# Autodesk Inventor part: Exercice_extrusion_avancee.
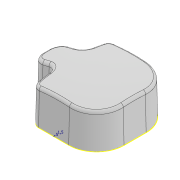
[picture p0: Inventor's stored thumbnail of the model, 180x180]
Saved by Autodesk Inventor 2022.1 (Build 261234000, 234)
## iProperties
Created: 2019-12
Part Number: Exercice_extrusion_avancee.
Material: Générique
Document SubType Name: Modeling
Designer: Fabian
Density: 1 g/cm^3
Appearance: Par défaut
Mass: 114.286 g
Surface Area: 775.892 cm^2
Volume: 114.286 cm^3
Author: Fabian
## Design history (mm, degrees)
sketch "Esquisse1"
  geometry: L1 (0, 70)-(0, -66.117); L2 (90, 0)-(-70, 0); L3 (90, 14.325)-(90, 0); L4 (-70, 45)-(-70, 0); L5 (44.578, 70)-(-45, 70); L6 (86.745, 24.649)-(60.961, 61.472); L7 (83, 0)-(83, 5); L8 (65, 23)-(55, 23); L9 (43, 35)-(43, 51); L10 (31, 63)-(-18, 63); L11 (-63, 18)-(-63, 0); L12 (-63, -18)-(-63, 0); L13 (0, -70)-(0, 66.117); L14 (-70, -45)-(-70, 0); L15 (31, -63)-(-18, -63); L16 (44.578, -70)-(-45, -70); L17 (43, -35)-(43, -51); L18 (90, -14.325)-(90, 0); L19 (86.745, -24.649)-(60.961, -61.472); L20 (83, 0)-(83, -5); L21 (65, -23)-(55, -23); C1 r 4 at (-60, 60); C2 r 6 at (55, 35); C3 r 4 at (-60, -60); C4 r 6 at (55, -35); A1 r 15 centre (-60, 60) between (-51, 72) and (-72, 51); A2 r 12 centre (55, 35) between (43, 35) and (55, 23); A3 r 12 centre (31, 51) between (43, 51) and (31, 63); A4 r 18 centre (72, 14.325) between (90, 14.325) and (86.745, 24.649); A5 r 20 centre (44.578, 50) between (60.961, 61.472) and (44.578, 70); A6 r 10 centre (-45, 80) between (-51, 72) and (-45, 70); A7 r 10 centre (-80, 45) between (-70, 45) and (-72, 51); A8 r 18 centre (65, 5) between (83, 5) and (65, 23); A9 r 45 centre (-18, 18) between (-18, 63) and (-63, 18); A10 r 45 centre (-18, -18) between (-63, -18) and (-18, -63); A11 r 12 centre (31, -51) between (31, -63) and (43, -51); A12 r 10 centre (-45, -80) between (-45, -70) and (-51, -72); A13 r 15 centre (-60, -60) between (-72, -51) and (-51, -72); A14 r 10 centre (-80, -45) between (-72, -51) and (-70, -45); A15 r 12 centre (55, -35) between (55, -23) and (43, -35); A16 r 20 centre (44.578, -50) between (44.578, -70) and (60.961, -61.472); A17 r 18 centre (65, -5) between (65, -23) and (83, -5); A18 r 18 centre (72, -14.325) between (86.745, -24.649) and (90, -14.325); 7 further points
  constraints: 44 end point, 40 point on circle, 32 symmetric about line, 22 centre point, 16 tangent, 14 point on line, 5 perpendicular, 4 coincident, 3 vertical, 2 horizontal, 11 other
  dimensions: "d2" = 70 distance between parallel lines of L4 L1; "d3" = 90 distance between parallel lines of L3 L1; "d5" = 30 diameter of A1; "d6" = 140 diameter of L5 L2; "d7" = 20 distance of point (90, 20) L2.start; "d8" = 35 deg angle of L3 L6; "d9" = 120 diameter of A1.centre L2; "d11" = 60 distance from line of A1.centre L1; "d12" = 8 diameter of C1; "d13" = 70 diameter of C2.centre L2; "d14" = 55 distance from line of C2.centre L1; "d15" = 12 diameter of C2; "d16" = 83 distance between parallel lines of L7 L1; "d17" = 63 distance between parallel lines of L11 L1; "d18" = 46 diameter of L8 L2 (derived); "d19" = 126 diameter of L10 L2; "d21" = 12 radius of A2; "d22" = 43 distance between parallel lines of L9 L1 (derived); "d23" = 12 radius of A3 (derived); "d24" = 18 radius of A4 (derived); "d25" = 20 radius of A5; "d26" = 10 radius of A6; "d27" = 10 radius of A7; "d28" = 18 radius of A8; "d29" = 45 radius of A9
extrude "Extrusion1" new body sketch "Esquisse1" distance "d30" = 65; taper "d31" = -1 deg
sketch "Esquisse2"
  geometry: L1 (-81.865, 65)-(61.865, 65); L2 (0, -455)-(0, 65); L3 (18, 65)-(-31, 65) reference; L4 (-55, 65)-(-65, 65) reference; A1 r 260 centre (0, -195) between (0, -455) and (0, 65); 1 further point
  constraints: 4 end point, 2 point on circle, 1 centre point, 1 collinear, 1 point on line, 1 tangent, 1 vertical, 1 vertical alignment
  dimensions: "d32" = 520 diameter of A1
revolve "Révolution1" sketch "Esquisse2" stored, may be unused: angle "d33" = 90 deg
fillet "Congé1" dims "d36" = 5
feature "Coque1" dims "d37" = 3
sketch "Esquisse3"
  geometry: L1 (-80, -5)-(-80, 5) reference; L2 (-65, 20)-(-55, 20) reference; L3 (-40, 35)-(-40, 51) reference; L4 (-31, 60)-(18, 60) reference; L5 (60, 18)-(60, -18) reference; L6 (18, -60)-(-31, -60) reference; L7 (-40, -51)-(-40, -35) reference; L8 (-55, -20)-(-65, -20) reference; L9 (-31, 63)-(18, 63) reference; L10 (-43, 35)-(-43, 51) reference; L11 (-65, 23)-(-55, 23) reference; L12 (-83, -5)-(-83, 5) reference; L13 (-55, -23)-(-65, -23) reference; L14 (-43, -51)-(-43, -35) reference; L15 (18, -63)-(-31, -63) reference; L16 (63, 18)-(63, -18) reference; L17 (18, 55)-(-31, 55); L18 (-35, 51)-(-35, 35); L19 (-55, 15)-(-65, 15); L20 (-75, 5)-(-75, -5); L21 (-65, -15)-(-55, -15); L22 (-35, -35)-(-35, -51); L23 (-31, -55)-(18, -55); L24 (55, -18)-(55, 18); L25 (-31, 56.5)-(18, 56.5); L26 (56.5, 18)-(56.5, -18); L27 (18, -56.5)-(-31, -56.5); L28 (-36.5, -51)-(-36.5, -35); L29 (-55, -16.5)-(-65, -16.5); L30 (-76.5, -5)-(-76.5, 5); L31 (-65, 16.5)-(-55, 16.5); L32 (-36.5, 35)-(-36.5, 51); A1 r 15 centre (-65, -5) between (-80, -5) and (-65, -20) reference; A2 r 15 centre (-65, 5) between (-65, 20) and (-80, 5) reference; A3 r 15 centre (-55, 35) between (-55, 20) and (-40, 35) reference; A4 r 9 centre (-31, 51) between (-31, 60) and (-40, 51) reference; A5 r 42 centre (18, 18) between (60, 18) and (18, 60) reference; A6 r 42 centre (18, -18) between (18, -60) and (60, -18) reference; A7 r 9 centre (-31, -51) between (-40, -51) and (-31, -60) reference; A8 r 15 centre (-55, -35) between (-40, -35) and (-55, -20) reference; A9 r 12 centre (-31, 51) between (-31, 63) and (-43, 51) reference; A10 r 12 centre (-55, 35) between (-55, 23) and (-43, 35) reference; A11 r 18 centre (-65, 5) between (-65, 23) and (-83, 5) reference; A12 r 18 centre (-65, -5) between (-83, -5) and (-65, -23) reference; A13 r 12 centre (-55, -35) between (-43, -35) and (-55, -23) reference; A14 r 12 centre (-31, -51) between (-43, -51) and (-31, -63) reference; A15 r 45 centre (18, -18) between (18, -63) and (63, -18) reference; A16 r 45 centre (18, 18) between (63, 18) and (18, 63) reference; A17 r 4 centre (-31, 51) between (-31, 55) and (-35, 51); A18 r 20 centre (-55, 35) between (-55, 15) and (-35, 35); A19 r 10 centre (-65, 5) between (-65, 15) and (-75, 5); A20 r 10 centre (-65, -5) between (-75, -5) and (-65, -15); A21 r 20 centre (-55, -35) between (-35, -35) and (-55, -15); A22 r 4 centre (-31, -51) between (-35, -51) and (-31, -55); A23 r 37 centre (18, -18) between (18, -55) and (55, -18); A24 r 37 centre (18, 18) between (55, 18) and (18, 55); A25 r 38.5 centre (18, 18) between (56.5, 18) and (18, 56.5); A26 r 38.5 centre (18, -18) between (18, -56.5) and (56.5, -18); A27 r 5.5 centre (-31, -51) between (-36.5, -51) and (-31, -56.5); A28 r 18.5 centre (-55, -35) between (-36.5, -35) and (-55, -16.5); A29 r 11.5 centre (-65, -5) between (-76.5, -5) and (-65, -16.5); A30 r 11.5 centre (-65, 5) between (-65, 16.5) and (-76.5, 5); A31 r 18.5 centre (-55, 35) between (-55, 16.5) and (-36.5, 35); A32 r 5.5 centre (-31, 51) between (-31, 56.5) and (-36.5, 51); 1 further point
  constraints: 32 end point, 32 point on circle, 16 centre point, 30 other
  dimensions: "d39" = 5 distance between parallel lines of L4 L17; "d40" = 1.5 distance between parallel lines of L17 L25
  node "Boucle projetée1"
node "Solide1"
